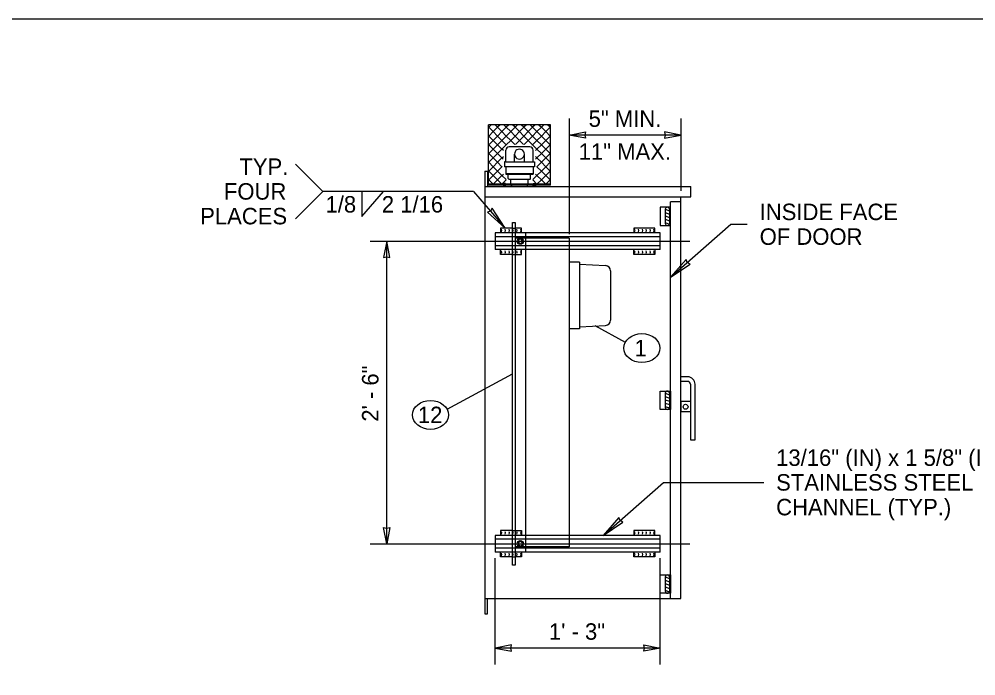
# Model space of a CAD drawing. Extents: x 99862 to 103680, y 99470 to 105076.
# Drawn here: x 100791 to 101720, y 104438 to 105076 of the extents above; entities that cross this region are included whole.
import ezdxf

# ---------------------------------------------------------------- set-up
doc = ezdxf.new("R2010")
doc.units = 0
for name, color, linetype in [('Level 1', 7, 'Continuous'), ('Level 15', 7, 'Continuous'), ('Level 20', 7, 'Continuous'), ('Level 40', 7, 'Continuous')]:
    doc.layers.add(name, color=color, linetype=linetype)

msp = doc.modelspace()

# ---------------------------------------------------------------- linework, layer by layer
at = {"layer": 'Level 1'}
for p, q in [((101246.46, 104915.18), (101246.46, 104972.94)), ((101306.46, 104972.94), (101246.46, 104972.94)), ((101246.46, 104970.71), (101246.68, 104970.49)), ((101246.68, 104970.49), (101246.46, 104970.26)), ((101246.68, 104970.49), (101249.13, 104972.94)), ((101250.93, 104966.23), (101246.68, 104970.49)), ((101255.19, 104970.49), (101250.93, 104966.23)), ((101252.74, 104972.94), (101255.19, 104970.49)), ((101257.64, 104972.94), (101255.19, 104970.49)), ((101255.19, 104970.49), (101259.44, 104966.23)), ((101259.44, 104966.23), (101263.7, 104970.49)), ((101263.7, 104970.49), (101261.24, 104972.94)), ((101266.15, 104972.94), (101263.7, 104970.49)), ((101263.7, 104970.49), (101267.95, 104966.23)), ((101267.95, 104966.23), (101272.21, 104970.49)), ((101272.21, 104970.49), (101269.75, 104972.94)), ((101274.66, 104972.94), (101272.21, 104970.49)), ((101272.21, 104970.49), (101276.46, 104966.23)), ((101276.46, 104966.23), (101280.71, 104970.49)), ((101280.71, 104970.49), (101278.26, 104972.94)), ((101283.17, 104972.94), (101280.71, 104970.49)), ((101280.71, 104970.49), (101284.97, 104966.23)), ((101284.97, 104966.23), (101289.22, 104970.49)), ((101289.22, 104970.49), (101286.77, 104972.94)), ((101291.67, 104972.94), (101289.22, 104970.49)), ((101289.22, 104970.49), (101293.48, 104966.23)), ((101293.48, 104966.23), (101297.73, 104970.49)), ((101295.28, 104972.94), (101297.73, 104970.49)), ((101297.73, 104970.49), (101300.18, 104972.94)), ((101297.73, 104970.49), (101301.98, 104966.23)), ((101301.98, 104966.23), (101306.24, 104970.49)), ((101306.24, 104970.49), (101303.79, 104972.94)), ((101306.46, 104970.71), (101306.24, 104970.49)), ((101306.24, 104970.49), (101306.46, 104970.27)), ((101306.46, 104915.18), (101306.46, 104972.94)), ((101246.46, 104962.2), (101246.68, 104961.98)), ((101246.68, 104961.98), (101246.46, 104961.76)), ((101246.68, 104961.98), (101250.93, 104966.23)), ((101250.93, 104957.72), (101246.68, 104961.98)), ((101250.93, 104966.23), (101255.19, 104961.98)), ((101255.19, 104961.98), (101250.93, 104957.72)), ((101259.44, 104966.23), (101255.19, 104961.98)), ((101255.19, 104961.98), (101259.44, 104957.72)), ((101263.7, 104961.98), (101259.44, 104966.23)), ((101259.44, 104957.72), (101263.7, 104961.98)), ((101267.95, 104966.23), (101263.7, 104961.98)), ((101263.7, 104961.98), (101267.95, 104957.72)), ((101272.21, 104961.98), (101267.95, 104966.23)), ((101267.95, 104957.72), (101272.21, 104961.98)), ((101276.46, 104966.23), (101272.21, 104961.98)), ((101272.21, 104961.98), (101276.46, 104957.72)), ((101280.71, 104961.98), (101276.46, 104966.23)), ((101276.46, 104957.72), (101280.71, 104961.98)), ((101284.97, 104966.23), (101280.71, 104961.98)), ((101280.71, 104961.98), (101284.97, 104957.72)), ((101289.22, 104961.98), (101284.97, 104966.23)), ((101284.97, 104957.72), (101289.22, 104961.98)), ((101293.48, 104966.23), (101289.22, 104961.98)), ((101289.22, 104961.98), (101293.48, 104957.72)), ((101297.73, 104961.98), (101293.48, 104966.23)), ((101293.48, 104957.72), (101297.73, 104961.98)), ((101301.98, 104966.23), (101297.73, 104961.98)), ((101297.73, 104961.98), (101301.98, 104957.72)), ((101306.24, 104961.98), (101301.98, 104966.23)), ((101301.98, 104957.72), (101306.24, 104961.98)), ((101306.46, 104962.2), (101306.24, 104961.98)), ((101306.24, 104961.98), (101306.46, 104961.76)), ((101246.46, 104953.69), (101246.68, 104953.47)), ((101246.68, 104953.47), (101246.46, 104953.25)), ((101246.68, 104953.47), (101250.93, 104957.72)), ((101250.93, 104949.22), (101246.68, 104953.47)), ((101250.93, 104957.72), (101255.19, 104953.47)), ((101255.19, 104953.47), (101250.93, 104949.22)), ((101259.44, 104957.72), (101255.19, 104953.47)), ((101255.19, 104953.47), (101259.44, 104949.22)), ((101263.7, 104953.47), (101259.44, 104957.72)), ((101259.44, 104949.22), (101263.7, 104953.47)), ((101267.95, 104957.72), (101263.7, 104953.47)), ((101263.7, 104953.47), (101263.91, 104953.25)), ((101286.49, 104951.44), (101266.43, 104951.44)), ((101271.83, 104953.85), (101267.95, 104957.72)), ((101276.46, 104957.72), (101272.59, 104953.85)), ((101280.33, 104953.85), (101276.46, 104957.72)), ((101284.97, 104957.72), (101281.09, 104953.85)), ((101289.22, 104953.47), (101284.97, 104957.72)), ((101289.01, 104953.25), (101289.22, 104953.47)), ((101293.48, 104957.72), (101289.22, 104953.47)), ((101289.22, 104953.47), (101293.48, 104949.22)), ((101297.73, 104953.47), (101293.48, 104957.72)), ((101293.48, 104949.22), (101297.73, 104953.47)), ((101301.98, 104957.72), (101297.73, 104953.47)), ((101297.73, 104953.47), (101301.98, 104949.22)), ((101306.24, 104953.47), (101301.98, 104957.72)), ((101301.98, 104949.22), (101306.24, 104953.47)), ((101306.46, 104953.69), (101306.24, 104953.47)), ((101306.24, 104953.47), (101306.46, 104953.25)), ((101246.46, 104945.18), (101246.68, 104944.96)), ((101246.68, 104944.96), (101246.46, 104944.74)), ((101246.68, 104944.96), (101250.93, 104949.22)), ((101250.93, 104940.71), (101246.68, 104944.96)), ((101246.68, 104936.45), (101250.93, 104940.71)), ((101250.93, 104949.22), (101255.19, 104944.96)), ((101255.19, 104944.96), (101250.93, 104940.71)), ((101250.93, 104940.71), (101255.19, 104936.45)), ((101259.44, 104949.22), (101255.19, 104944.96)), ((101255.19, 104944.96), (101259.44, 104940.71)), ((101259.44, 104940.71), (101255.19, 104936.45)), ((101260.82, 104947.84), (101259.44, 104949.22)), ((101259.44, 104940.71), (101260.82, 104942.08)), ((101260.74, 104939.41), (101259.44, 104940.71)), ((101263.22, 104937), (101263.22, 104948.23)), ((101271.65, 104937), (101271.65, 104944.38)), ((101281.27, 104937), (101281.27, 104944.38)), ((101289.69, 104937), (101289.69, 104948.23)), ((101293.48, 104949.22), (101292.1, 104947.84)), ((101292.1, 104942.08), (101293.48, 104940.71)), ((101293.48, 104940.71), (101292.18, 104939.41)), ((101297.73, 104944.96), (101293.48, 104949.22)), ((101293.48, 104940.71), (101297.73, 104944.96)), ((101297.73, 104936.45), (101293.48, 104940.71)), ((101301.98, 104949.22), (101297.73, 104944.96)), ((101297.73, 104944.96), (101301.98, 104940.71)), ((101301.98, 104940.71), (101297.73, 104936.45)), ((101306.24, 104944.96), (101301.98, 104949.22)), ((101301.98, 104940.71), (101306.24, 104944.96)), ((101306.24, 104936.45), (101301.98, 104940.71)), ((101306.46, 104945.18), (101306.24, 104944.96)), ((101306.24, 104944.96), (101306.46, 104944.74)), ((101246.46, 104936.67), (101246.68, 104936.45)), ((101246.68, 104936.45), (101246.46, 104936.23)), ((101250.93, 104932.2), (101246.68, 104936.45)), ((101246.68, 104927.94), (101250.93, 104932.2)), ((101255.19, 104936.45), (101250.93, 104932.2)), ((101250.93, 104932.2), (101255.19, 104927.94)), ((101255.19, 104936.45), (101259.44, 104932.2)), ((101259.44, 104932.2), (101255.19, 104927.94)), ((101259.44, 104932.2), (101259.61, 104932.37)), ((101259.61, 104932.03), (101259.44, 104932.2)), ((101263.22, 104937), (101262.02, 104937)), ((101262.02, 104937), (101262.02, 104932.19)), ((101290.9, 104932.19), (101262.02, 104932.19)), ((101263.22, 104937), (101289.69, 104937)), ((101263.22, 104932.19), (101263.22, 104924.97)), ((101289.69, 104937), (101290.9, 104937)), ((101289.69, 104932.19), (101289.69, 104924.97)), ((101290.9, 104937), (101290.9, 104932.19)), ((101293.3, 104932.37), (101293.48, 104932.2)), ((101293.48, 104932.2), (101293.3, 104932.03)), ((101293.48, 104932.2), (101297.73, 104936.45)), ((101297.73, 104927.94), (101293.48, 104932.2)), ((101297.73, 104936.45), (101301.98, 104932.2)), ((101301.98, 104932.2), (101297.73, 104927.94)), ((101301.98, 104932.2), (101306.24, 104936.45)), ((101306.24, 104927.94), (101301.98, 104932.2)), ((101306.46, 104936.67), (101306.24, 104936.45)), ((101306.24, 104936.45), (101306.46, 104936.23)), ((101246.46, 104928.17), (101246.68, 104927.94)), ((101246.68, 104927.94), (101246.46, 104927.72)), ((101250.93, 104923.69), (101246.68, 104927.94)), ((101246.68, 104919.44), (101250.93, 104923.69)), ((101255.19, 104927.94), (101250.93, 104923.69)), ((101250.93, 104923.69), (101255.19, 104919.44)), ((101255.19, 104927.94), (101259.44, 104923.69)), ((101259.44, 104923.69), (101255.19, 104919.44)), ((101259.44, 104923.69), (101260.82, 104925.06)), ((101263.41, 104919.73), (101259.44, 104923.69)), ((101263.22, 104925.57), (101289.69, 104925.57)), ((101263.22, 104924.97), (101289.69, 104924.97)), ((101265.63, 104920.76), (101265.63, 104924.97)), ((101287.29, 104920.76), (101287.29, 104924.97)), ((101293.48, 104923.69), (101289.51, 104919.73)), ((101292.1, 104925.07), (101293.48, 104923.69)), ((101293.48, 104923.69), (101297.73, 104927.94)), ((101297.73, 104919.44), (101293.48, 104923.69)), ((101297.73, 104927.94), (101301.98, 104923.69)), ((101301.98, 104923.69), (101297.73, 104919.44)), ((101301.98, 104923.69), (101306.24, 104927.94)), ((101306.24, 104919.44), (101301.98, 104923.69)), ((101306.46, 104928.16), (101306.24, 104927.94)), ((101306.24, 104927.94), (101306.46, 104927.72)), ((101246.46, 104919.66), (101246.68, 104919.44)), ((101246.68, 104919.44), (101246.46, 104919.21)), ((101306.46, 104915.18), (101246.46, 104915.18)), ((101246.46, 104914.14), (101246.46, 104915.08)), ((101306.46, 104915.08), (101246.46, 104915.08)), ((101306.46, 104914.14), (101246.46, 104914.14)), ((101250.93, 104915.18), (101246.68, 104919.44)), ((101255.19, 104919.44), (101250.93, 104915.18)), ((101255.19, 104919.44), (101259.44, 104915.18)), ((101259.44, 104915.18), (101263.59, 104919.33)), ((101266.23, 104920.16), (101286.69, 104920.16)), ((101268.04, 104915.35), (101268.04, 104920.16)), ((101270.44, 104912.94), (101282.48, 104912.94)), ((101284.88, 104915.35), (101284.88, 104920.16)), ((101289.33, 104919.33), (101293.48, 104915.18)), ((101293.48, 104915.18), (101297.73, 104919.44)), ((101297.73, 104919.44), (101301.98, 104915.18)), ((101301.98, 104915.18), (101306.24, 104919.44)), ((101306.46, 104919.66), (101306.24, 104919.44)), ((101306.24, 104919.44), (101306.46, 104919.22)), ((101306.46, 104914.14), (101306.46, 104915.08)), ((101417.96, 104890.87), (101417.96, 104877.1)), ((101417.96, 104890.87), (101421.96, 104889.32)), ((101417.96, 104887.65), (101421.96, 104886.11)), ((101421.96, 104890.87), (101421.96, 104877.1)), ((101422.96, 104875.1), (101422.96, 104892.87)), ((101269.69, 104610.43), (101269.69, 104877.94)), ((101269.69, 104877.94), (101272.27, 104877.94)), ((101272.27, 104877.94), (101272.27, 104545.24)), ((101417.96, 104884.44), (101421.96, 104882.89)), ((101417.96, 104881.22), (101421.96, 104879.68)), ((101417.96, 104878), (101421.87, 104876.5)), ((101257.96, 104872.61), (101257.96, 104867.94)), ((101269.69, 104872.61), (101257.96, 104872.61)), ((101269.69, 104872.61), (101272.27, 104872.61)), ((101278.58, 104872.61), (101272.27, 104872.61)), ((101278.58, 104867.94), (101278.58, 104872.61)), ((101407.96, 104872.61), (101387.33, 104872.61)), ((101387.33, 104872.61), (101387.33, 104867.94)), ((101407.96, 104867.94), (101407.96, 104872.61)), ((101131.58, 104859.81), (101441.86, 104859.81)), ((101324.77, 104862.94), (101272.27, 104862.94)), ((101272.27, 104862.94), (101272.27, 104562.94)), ((101324.77, 104862.94), (101324.77, 104562.94)), ((101257.96, 104847.02), (101257.96, 104851.69)), ((101278.58, 104847.02), (101278.58, 104851.69)), ((101387.33, 104847.02), (101387.33, 104851.69)), ((101407.96, 104851.69), (101407.96, 104847.02)), ((101269.69, 104847.02), (101257.96, 104847.02)), ((101269.69, 104847.02), (101278.58, 104847.02)), ((101334.77, 104839.62), (101324.77, 104839.62)), ((101334.77, 104839.62), (101334.77, 104774.62)), ((101407.96, 104847.02), (101387.33, 104847.02)), ((101334.77, 104837.59), (101360.06, 104836.11)), ((101364.77, 104831.12), (101364.77, 104783.12)), ((101334.77, 104774.62), (101324.77, 104774.62)), ((101334.77, 104776.66), (101360.06, 104778.13)), ((101439.69, 104728.16), (101432.96, 104728.16)), ((101439.69, 104723.73), (101432.96, 104723.73)), ((101442.51, 104720.91), (101442.51, 104666.86)), ((101446.94, 104666.86), (101446.94, 104720.91)), ((101417.96, 104712.32), (101417.96, 104698.55)), ((101417.96, 104712.32), (101421.96, 104710.78)), ((101417.96, 104709.11), (101421.96, 104707.57)), ((101421.96, 104712.32), (101421.96, 104698.55)), ((101422.96, 104714.32), (101422.96, 104696.55)), ((101417.96, 104705.89), (101421.96, 104704.35)), ((101417.96, 104702.68), (101421.96, 104701.14)), ((101417.96, 104699.46), (101421.87, 104697.96)), ((101442.51, 104704.07), (101432.96, 104704.07)), ((101432.96, 104704.07), (101432.96, 104694.07)), ((101442.51, 104694.07), (101432.96, 104694.07)), ((101442.51, 104666.86), (101446.94, 104666.86)), ((101269.69, 104545.24), (101269.69, 104610.43)), ((101257.96, 104578.86), (101257.96, 104574.19)), ((101269.69, 104578.86), (101257.96, 104578.86)), ((101269.69, 104578.86), (101278.58, 104578.86)), ((101278.58, 104578.86), (101278.58, 104574.19)), ((101407.96, 104578.86), (101387.33, 104578.86)), ((101387.33, 104578.86), (101387.33, 104574.19)), ((101407.96, 104574.19), (101407.96, 104578.86)), ((101131.58, 104566.06), (101441.86, 104566.06)), ((101324.77, 104562.94), (101272.27, 104562.94)), ((101257.96, 104553.27), (101257.96, 104557.94)), ((101269.69, 104553.27), (101257.96, 104553.27)), ((101269.69, 104553.27), (101272.27, 104553.27)), ((101278.58, 104553.27), (101272.27, 104553.27)), ((101278.58, 104557.94), (101278.58, 104553.27)), ((101387.33, 104553.27), (101387.33, 104557.94)), ((101407.96, 104553.27), (101387.33, 104553.27)), ((101407.96, 104557.94), (101407.96, 104553.27)), ((101272.27, 104545.24), (101269.69, 104545.24)), ((101417.96, 104533.78), (101417.96, 104520.01)), ((101417.96, 104533.78), (101421.96, 104532.24)), ((101421.96, 104533.78), (101421.96, 104520.01)), ((101422.96, 104535.78), (101422.96, 104518.01)), ((101417.96, 104530.57), (101421.96, 104529.02)), ((101417.96, 104527.35), (101421.96, 104525.81)), ((101417.96, 104524.14), (101421.96, 104522.59)), ((101417.96, 104520.92), (101421.87, 104519.41))]:
    msp.add_line(p, q, dxfattribs=at)
msp.add_lwpolyline([(99862, 102999.5), (103151, 102999.5), (103151, 105075.5), (99862, 105075.5)], close=True, dxfattribs=at)
for points in [[(101422.96, 104892.87), (101412.96, 104892.87), (101412.96, 104875.1), (101422.96, 104875.1)], [(101422.96, 104696.55), (101412.96, 104696.55), (101412.96, 104714.32), (101422.96, 104714.32)], [(101422.96, 104518.01), (101412.96, 104518.01), (101412.96, 104535.78), (101422.96, 104535.78)]]:
    msp.add_lwpolyline(points, dxfattribs=at)
msp.add_circle((101437.73, 104699.07), 2.37, dxfattribs=at)
for centre, radius, start, end in [((101266.43, 104948.23), 3.21, 90, 180), ((101286.49, 104948.23), 3.21, 0, 90), ((101276.46, 104944.38), 4.81, 359.99971, 180), ((101276.46, 104944.38), 4.81, 180, 0.00029), ((101266.23, 104920.76), 0.602, 180, 270), ((101270.44, 104915.35), 2.41, 180, 270), ((101282.48, 104915.35), 2.41, 270, 0), ((101286.69, 104920.76), 0.602, 270, 0), ((101419.96, 104890.87), 2, 90, 180), ((101419.96, 104890.87), 2, 0, 90), ((101419.96, 104877.1), 2, 180, 270), ((101419.96, 104877.1), 2, 270, 0), ((101257, 104870.28), 2.25, 327.42229, 32.57771), ((101260.75, 104870.28), 2.25, 327.42229, 32.57771), ((101264.5, 104870.28), 2.25, 327.42229, 32.57771), ((101268.25, 104870.28), 2.25, 327.42229, 32.57771), ((101272, 104870.28), 2.25, 327.42229, 32.57771), ((101275.75, 104870.28), 2.25, 327.42229, 32.57771), ((101386.38, 104870.28), 2.25, 327.42229, 32.57771), ((101390.13, 104870.28), 2.25, 327.42229, 32.57771), ((101393.88, 104870.28), 2.25, 327.42229, 32.57771), ((101397.63, 104870.28), 2.25, 327.42229, 32.57771), ((101401.38, 104870.28), 2.25, 327.42229, 32.57771), ((101405.13, 104870.28), 2.25, 327.42229, 32.57771), ((101257, 104849.35), 2.25, 327.42229, 32.57771), ((101260.75, 104849.35), 2.25, 327.42229, 32.57771), ((101264.5, 104849.35), 2.25, 327.42229, 32.57771), ((101268.25, 104849.35), 2.25, 327.42229, 32.57771), ((101272, 104849.35), 2.25, 327.42229, 32.57771), ((101275.75, 104849.35), 2.25, 327.42229, 32.57771), ((101386.38, 104849.35), 2.25, 327.42229, 32.57771), ((101390.13, 104849.35), 2.25, 327.42229, 32.57771), ((101393.88, 104849.35), 2.25, 327.42229, 32.57771), ((101397.63, 104849.35), 2.25, 327.42229, 32.57771), ((101401.38, 104849.35), 2.25, 327.42229, 32.57771), ((101405.13, 104849.35), 2.25, 327.42229, 32.57771), ((101359.77, 104831.12), 5, 360, 86.6576), ((101359.77, 104783.12), 5, 273.3424, 0), ((101439.69, 104720.91), 7.25, 0, 90), ((101439.69, 104720.91), 2.82, 0, 90), ((101419.96, 104712.32), 2, 90, 180), ((101419.96, 104712.32), 2, 0, 90), ((101419.96, 104698.55), 2, 180, 270), ((101419.96, 104698.55), 2, 270, 0), ((101257, 104576.53), 2.25, 327.42229, 32.57771), ((101260.75, 104576.53), 2.25, 327.42229, 32.57771), ((101264.5, 104576.53), 2.25, 327.42229, 32.57771), ((101268.25, 104576.53), 2.25, 327.42229, 32.57771), ((101272, 104576.53), 2.25, 327.42229, 32.57771), ((101275.75, 104576.53), 2.25, 327.42229, 32.57771), ((101386.38, 104576.53), 2.25, 327.42229, 32.57771), ((101390.13, 104576.53), 2.25, 327.42229, 32.57771), ((101393.88, 104576.53), 2.25, 327.42229, 32.57771), ((101397.63, 104576.53), 2.25, 327.42229, 32.57771), ((101401.38, 104576.53), 2.25, 327.42229, 32.57771), ((101405.13, 104576.53), 2.25, 327.42229, 32.57771), ((101257, 104555.6), 2.25, 327.42229, 32.57771), ((101260.75, 104555.6), 2.25, 327.42229, 32.57771), ((101264.5, 104555.6), 2.25, 327.42229, 32.57771), ((101268.25, 104555.6), 2.25, 327.42229, 32.57771), ((101272, 104555.6), 2.25, 327.42229, 32.57771), ((101275.75, 104555.6), 2.25, 327.42229, 32.57771), ((101386.38, 104555.6), 2.25, 327.42229, 32.57771), ((101390.13, 104555.6), 2.25, 327.42229, 32.57771), ((101393.88, 104555.6), 2.25, 327.42229, 32.57771), ((101397.63, 104555.6), 2.25, 327.42229, 32.57771), ((101401.38, 104555.6), 2.25, 327.42229, 32.57771), ((101405.13, 104555.6), 2.25, 327.42229, 32.57771), ((101419.96, 104533.78), 2, 90, 180), ((101419.96, 104533.78), 2, 0, 90), ((101419.96, 104520.01), 2, 180, 270), ((101419.96, 104520.01), 2, 270, 0)]:
    msp.add_arc(centre, radius, start, end, dxfattribs=at)
at = {"layer": 'Level 15'}
for p, q in [((101324.77, 104978.87), (101324.77, 104866.55)), ((101432.96, 104978.87), (101432.96, 104908.69)), ((101432.96, 104962.87), (101324.77, 104962.87)), ((101242.96, 104927.94), (101245.46, 104927.94)), ((101245.46, 104927.94), (101245.46, 104912.94)), ((101242.96, 104902.94), (101442.96, 104902.94)), ((101422.96, 104512.94), (101422.96, 104897.94)), ((101432.96, 104897.94), (101422.96, 104897.94)), ((101422.96, 104824.85), (101481.63, 104876.32)), ((101481.63, 104876.32), (101497.63, 104876.32)), ((101147.58, 104566.06), (101147.58, 104859.81)), ((101379.29, 104761.63), (101349.89, 104777.54)), ((101206.22, 104696.71), (101269.69, 104731.03)), ((101357.73, 104574.19), (101416.4, 104625.65)), ((101416.4, 104625.65), (101513.63, 104625.65)), ((101252.96, 104448.81), (101252.96, 104552.19)), ((101412.96, 104448.81), (101412.96, 104552.19)), ((101245.46, 104497.94), (101245.46, 104512.94)), ((101242.96, 104497.94), (101245.46, 104497.94)), ((101412.96, 104464.81), (101252.96, 104464.81))]:
    msp.add_line(p, q, dxfattribs=at)
for points in [[(101324.77, 104962.87), (101340.49, 104965.96), (101339.77, 104962.87), (101340.49, 104959.79)], [(101432.96, 104962.87), (101417.23, 104965.96), (101417.96, 104962.87), (101417.23, 104959.79)], [(101262.45, 104872.61), (101249.83, 104891.87), (101248.25, 104889.12), (101245.3, 104887.97)], [(101147.58, 104859.81), (101144.5, 104844.09), (101147.58, 104844.82), (101150.66, 104844.09)], [(101422.96, 104824.85), (101442.09, 104837.66), (101439.33, 104839.21), (101438.15, 104842.15)], [(101357.73, 104574.19), (101376.86, 104587), (101374.1, 104588.55), (101372.93, 104591.49)], [(101147.58, 104566.06), (101144.5, 104581.79), (101147.58, 104581.06), (101150.66, 104581.79)], [(101252.96, 104464.81), (101268.68, 104461.73), (101267.96, 104464.81), (101268.68, 104467.9)], [(101412.96, 104464.81), (101397.23, 104461.73), (101397.96, 104464.81), (101397.23, 104467.9)]]:
    msp.add_lwpolyline(points, close=True, dxfattribs=at)
at = {"layer": 'Level 20'}
for centre in [(101395.35, 104756.07), (101190.16, 104691.15)]:
    msp.add_ellipse(centre, major_axis=(-17.5, 0), ratio=0.8, dxfattribs=at)
at = {"layer": 'Level 40'}
for p, q in [((101085.67, 104908.22), (101059.17, 104934.73)), ((101242.96, 104927.94), (101242.96, 104497.94)), ((101242.96, 104912.94), (101442.96, 104912.94)), ((101442.96, 104902.94), (101442.96, 104912.94)), ((101085.67, 104908.22), (101059.17, 104881.72)), ((101231.82, 104908.22), (101085.67, 104908.22)), ((101123.5, 104883.88), (101144.54, 104908.22)), ((101123.5, 104908.22), (101123.5, 104883.88)), ((101231.82, 104908.22), (101262.45, 104872.61)), ((101432.96, 104512.94), (101432.96, 104902.94)), ((101269.69, 104867.94), (101252.96, 104867.94)), ((101252.96, 104867.94), (101252.96, 104851.69)), ((101272.27, 104867.94), (101269.69, 104867.94)), ((101412.96, 104867.94), (101272.27, 104867.94)), ((101282.27, 104867.94), (101282.27, 104862.94)), ((101412.96, 104851.69), (101412.96, 104867.94)), ((101269.69, 104864.19), (101252.96, 104864.19)), ((101273.05, 104864.19), (101269.69, 104864.19)), ((101412.96, 104864.19), (101273.05, 104864.19)), ((101282.27, 104862.94), (101282.27, 104562.94)), ((101269.69, 104855.44), (101252.96, 104855.44)), ((101269.69, 104851.69), (101252.96, 104851.69)), ((101324.77, 104855.44), (101269.69, 104855.44)), ((101324.77, 104851.69), (101269.69, 104851.69)), ((101412.96, 104855.44), (101324.77, 104855.44)), ((101412.96, 104851.69), (101324.77, 104851.69)), ((101269.69, 104574.19), (101252.96, 104574.19)), ((101252.96, 104574.19), (101252.96, 104557.94)), ((101269.69, 104570.44), (101252.96, 104570.44)), ((101324.77, 104574.19), (101269.69, 104574.19)), ((101324.77, 104570.44), (101269.69, 104570.44)), ((101412.96, 104574.19), (101324.77, 104574.19)), ((101412.96, 104570.44), (101324.77, 104570.44)), ((101412.96, 104557.94), (101412.96, 104574.19)), ((101269.69, 104561.69), (101252.96, 104561.69)), ((101272.27, 104561.69), (101269.69, 104561.69)), ((101412.96, 104561.69), (101272.27, 104561.69)), ((101282.27, 104562.94), (101282.27, 104557.94)), ((101269.69, 104557.94), (101252.96, 104557.94)), ((101272.27, 104557.94), (101269.69, 104557.94)), ((101412.96, 104557.94), (101272.27, 104557.94)), ((101242.96, 104512.94), (101432.96, 104512.94))]:
    msp.add_line(p, q, dxfattribs=at)
for points in [[(101263.36, 104913.18), (101263.36, 104912.94), (101260.68, 104912.94), (101260.68, 104913.18)], [(101263.33, 104913.35), (101263.33, 104913.18), (101260.71, 104913.18), (101260.71, 104913.35)], [(101263, 104915.1), (101263, 104915.88), (101261.04, 104915.88), (101261.04, 104915.1)], [(101263, 104913.35), (101263, 104914.14), (101261.04, 104914.14), (101261.04, 104913.35)], [(101289.55, 104913.18), (101289.55, 104912.94), (101292.24, 104912.94), (101292.24, 104913.18)], [(101289.58, 104913.35), (101289.58, 104913.18), (101292.21, 104913.18), (101292.21, 104913.35)], [(101289.91, 104915.1), (101289.91, 104915.88), (101291.88, 104915.88), (101291.88, 104915.1)], [(101289.91, 104913.35), (101289.91, 104914.14), (101291.88, 104914.14), (101291.88, 104913.35)], [(101278.82, 104858.13), (101279.5, 104860.32), (101277.95, 104862), (101275.71, 104861.49), (101275.04, 104859.31), (101276.59, 104857.63)], [(101278.82, 104564.38), (101279.5, 104566.57), (101277.95, 104568.25), (101275.71, 104567.74), (101275.04, 104565.56), (101276.59, 104563.88)]]:
    msp.add_lwpolyline(points, close=True, dxfattribs=at)
for centre in [(101277.27, 104859.81), (101277.27, 104566.06)]:
    msp.add_circle(centre, 2.99, dxfattribs=at)

# ---------------------------------------------------------------- texts
at = {"layer": 'Level 20'}
for s, rotation, p in [('5" MIN.', 360, (101343.62, 104970.87)), ('11" MAX.', 0, (101333.94, 104938.87)), ('TYP.', 360, (101004.56, 104924.22)), ('FOUR', 360, (100989.54, 104900.22)), ('PLACES', 360, (100966.5, 104876.22)), ('2\' - 6"', 90, (101139.58, 104684.6)), ('1\' - 3"', 360, (101305.08, 104472.81))]:
    msp.add_text(s, height=16, rotation=rotation, dxfattribs=at).set_placement(p)
for s, p in [('1/8', (101088.19, 104887.66)), ('2 1/16', (101142.87, 104887.66)), ('INSIDE FACE', (101509.63, 104880.32)), ('OF DOOR', (101509.63, 104856.32)), ('1', (101388.2, 104748.07)), ('12', (101177.83, 104683.15)), ('13/16" (IN) x 1 5/8" (IN)', (101525.63, 104641.65)), ('STAINLESS STEEL', (101525.63, 104617.65)), ('CHANNEL (TYP.)', (101525.63, 104593.65))]:
    msp.add_text(s, height=16, dxfattribs=at).set_placement(p)

doc.saveas('drawing.dxf')
